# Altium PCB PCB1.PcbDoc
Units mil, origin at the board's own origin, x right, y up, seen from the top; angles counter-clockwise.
Board outline 1377.95 x 2381.89 mil, 2 copper layers (Top Layer, Bottom Layer), stack 65.792 mil thick; 17 components, 12 nets, 45 pads, 0 vias.
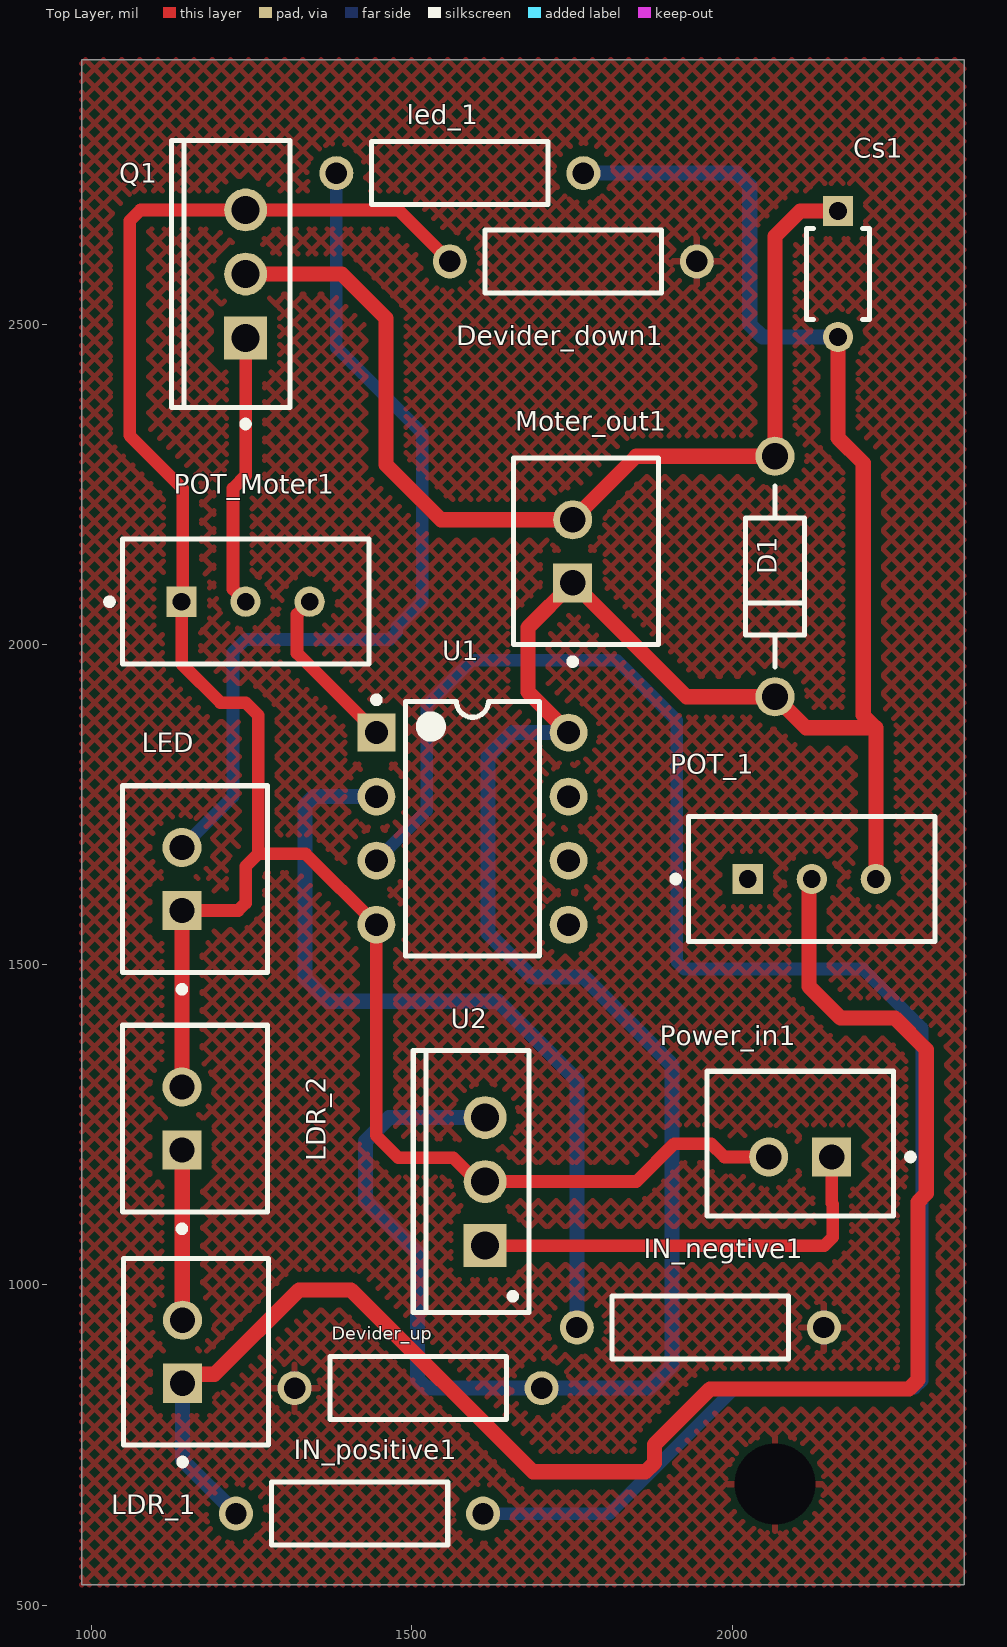
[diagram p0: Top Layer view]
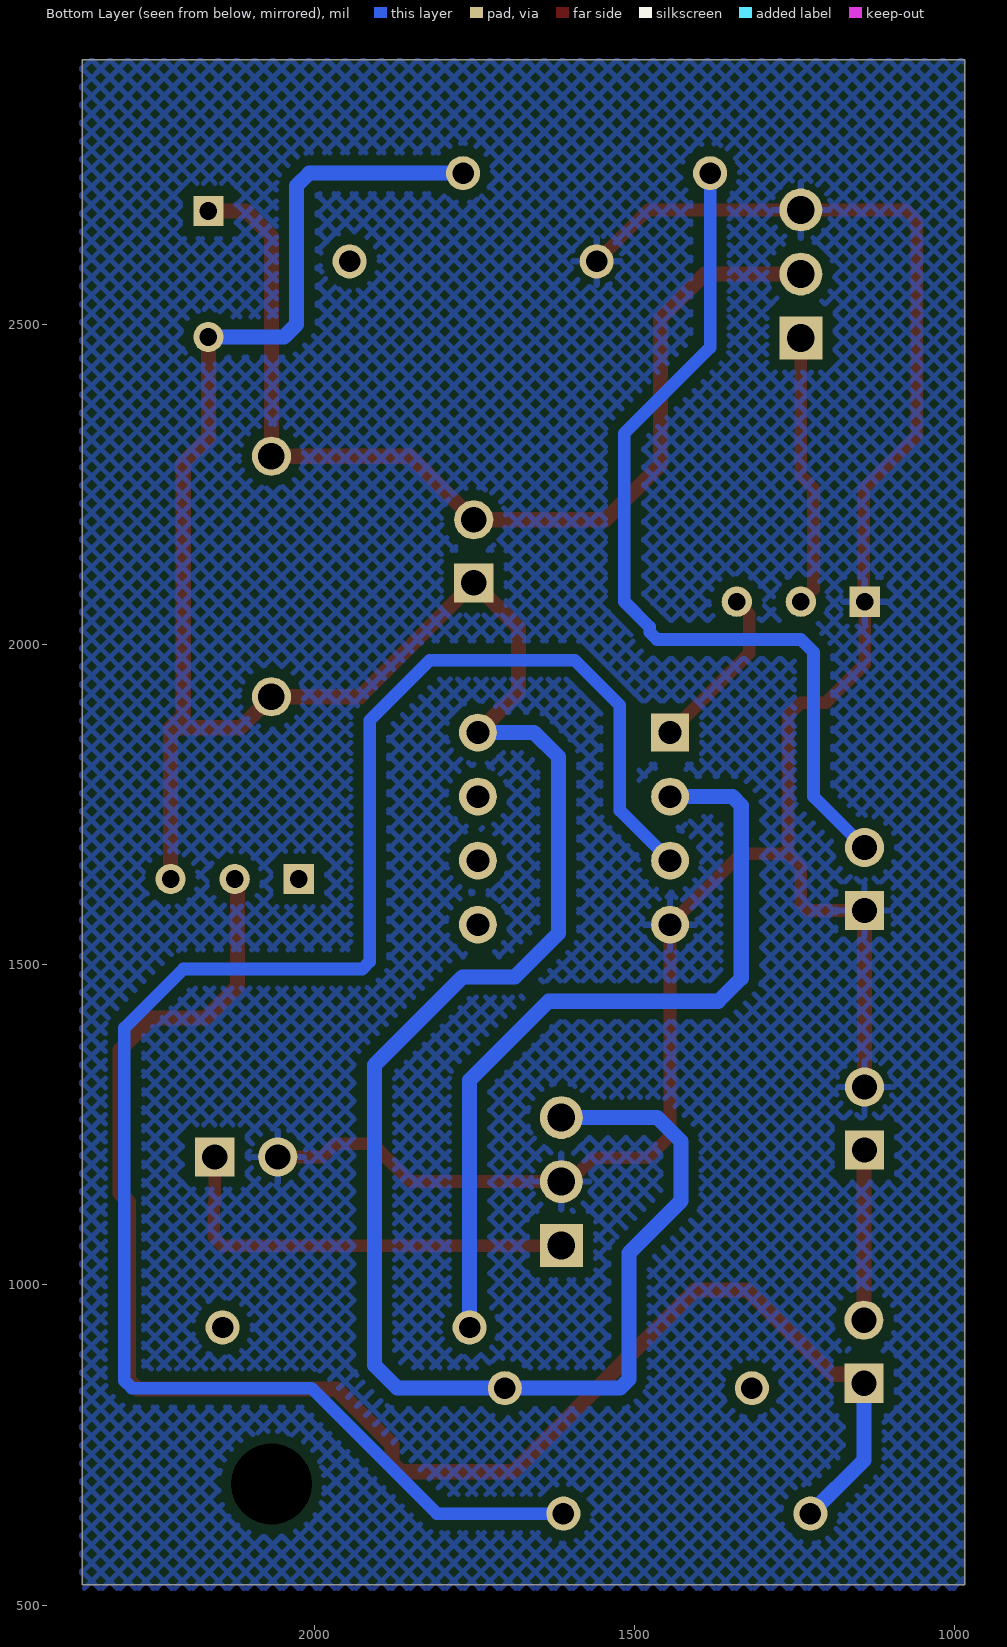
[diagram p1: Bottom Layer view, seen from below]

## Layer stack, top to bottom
Top Solder: solder mask 0.4, Solder Resist, Dk 3.5
Top Layer: signal copper 1.4
Dielectric 1: dielectric 62.9921, FR-4, Dk 4.8
Bottom Layer: signal copper 1.4
Bottom Solder: solder mask 0.4, Solder Resist, Dk 3.5

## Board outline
984.25,531.5 2362.2,531.5 2362.2,2913.39 984.25,2913.39

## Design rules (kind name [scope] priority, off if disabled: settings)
Clearance [All] p1: gap=15.75 ignorepadtopadclearanceinfootprint=FALSE
PolygonConnect [All] p1: connectstyle=Relief reliefconductorwidth=10 reliefentries=4 polygonreliefangle="90 Angle" airgapwidth=10
RoutingVias [All] p1: holewidth=27.56 width=39.37 viastyle="Through Hole" minholewidth=27.56 minwidth=39.37 maxholewidth=27.56 maxwidth=78.74
SilkToSolderMaskClearance [IsPad] p1: minsilkscreentomaskgap=7.87 clearancetoexposedcopper=TRUE
SolderMaskExpansion [All] p1: expansion=4 istentingtop=FALSE
Width [All] p1: maxlimit=78.74 minlimit=19.68 preferedwidth=39.37
29 further rules are at their usual default settings.

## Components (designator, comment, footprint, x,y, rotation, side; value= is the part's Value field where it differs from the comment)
Cs1 "27pF" FP-RCE0K1-MFG 2165.35,2578.74 r270 top
D1 "1N5819" ONSC-AXIAL_LEAD-2-59-10_P 2066.93,2106.3 r90 top
Devider_down1 "10K" OMTE-RES7X2.5-2 1751.97,2598.43 r0 top
Devider_up "10K" OMTE-RES7X2.5-2 1509.5,838.78 r0 top (schematic designator Devider_up1)
IN_negtive1 "10K" OMTE-RES7X2.5-2 1950.39,933.49 r180 top
IN_positive1 "10K" OMTE-RES7X2.5-2 1418.06,642.83 r0 top
LDR_1 "LDR_1" FP-B2B-XH-A_LF_SN-MFG 1162.4,895.67 r90 top
LDR_2 "Signal" FP-B2B-XH-A_LF_SN-MFG 1161.42,1259.84 r90 top
LED "LED" FP-B2B-XH-A_LF_SN-MFG 1161.42,1633.86 r90 top
led_1 "10K" OMTE-RES7X2.5-2 1574.8,2736.22 r0 top
Moter_out1 "moter" FP-B2B-XH-A_LF_SN-MFG 1771.65,2145.67 r90 top
POT_1 "10K" FP-3296W-MFG 2124.41,1634.06 r270 top
POT_Moter1 "10K" FP-3296W-MFG 1240.16,2067.13 r270 top
Power_in1 "Power" FP-B2B-XH-A_LF_SN-MFG 2106.3,1220.47 r180 top
Q1 "IRF840PBF" VISH-TO-220AB-3 1240.16,2578.74 r180 top
U1 "LM358N" ONSC-PDIP-8-626-05_M 1594.49,1712.6 r0 top
U2 "L7805CV" TO220 1614.17,1161.42 r90 top

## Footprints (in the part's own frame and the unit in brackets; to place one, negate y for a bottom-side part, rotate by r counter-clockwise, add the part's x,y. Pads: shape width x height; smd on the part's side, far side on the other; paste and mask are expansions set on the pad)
FP-3296W-MFG [mm]
  rect 1.2x1.2 hole 0.7 paste-1000 mask+0: 1(0.005,-2.54)
  round 1.2 hole 0.7 paste-1000 mask+0: 2(0.005,0) 3(0.005,2.54)
  silkscreen extent -2.48,-5.52 2.48,4.89, body extent -2.58,-4.99 2.58,4.99, height 0.25
FP-B2B-XH-A_LF_SN-MFG [mm]
  rect 1.55x1.55 hole 1 paste-1000 mask+0: 1(-1.25,0.525)
  round 1.55 hole 1 paste-1000 mask+0: 2(1.25,0.525)
  silkscreen extent -4.5,-2.88 3.7,2.88, body extent -3.8,-2.98 3.8,2.98, height 0.25
FP-RCE0K1-MFG [mm]
  rect 1.2x1.2 hole 0.7 paste-1000 mask+0: 1(-2.5,0)
  round 1.2 hole 0.7 paste-1000 mask+0: 2(2.5,0)
  silkscreen extent -1.8,-1.25 1.8,1.25, body extent -3.2,-1.35 3.2,1.35, height 0.25
OMTE-RES7X2.5-2 [mm] "Resistor, Axial; Body 7x2.5mm, Lead Dia. 0.6mm"
  round 1.35 hole 0.85: 1(-4.9,0) 2(4.9,0)
  silkscreen extent -3.5,-1.25 3.5,1.25, body extent -3.5,-1.25 3.5,1.25, height 2.5
ONSC-AXIAL_LEAD-2-59-10_P [mm] "AXIAL, 2-Leads, Diameter 2.35mm"
  round 1.55 hole 1.05: 1(-4.77,0) 2(4.77,0)
  silkscreen extent -3.59,-1.17 3.59,1.17
ONSC-PDIP-8-626-05_M [mm] "DIP, 8-Leads, Body 10x7.1mm, Pitch 2.54mm"
  rect 1.5x1.5 hole 0.9: 1(-3.81,3.81)
  round 1.5 hole 0.9: 2(-3.81,1.27) 3(-3.81,-1.27) 4(-3.81,-3.81) 5(3.81,-3.81) 6(3.81,-1.27) 7(3.81,1.27) 8(3.81,3.81)
  silkscreen extent -3.93,-5.05 2.65,5.23, body extent -3.95,-5 3.95,5, height 5.33
TO220 [mm] "TO, Thru-Hole, Vertical, Heatsink Mounted; 3 In-Line Leads; Pitch 2.54 mm"
  rect 1.7x1.7 hole 1.1: 1(-2.54,0)
  round 1.7 hole 1.1: 2(0,0) 3(2.54,0)
  silkscreen extent -5.2,-1.75 5.2,2.85, body extent -5.25,-1.8 5.25,2.9, height 19.7
VISH-TO-220AB-3 [mm] "FM, 3-Leads, Body 10.55x4.65mm, Pitch 2.54mm"
  rect 1.7x1.7 hole 1.1: 1(0,2.54)
  round 1.7 hole 1.1: 2(0,0) 3(0,-2.54)
  silkscreen extent -1.77,-5.3 2.94,6.07, body extent -1.74,-5.28 2.91,5.28, height 19.31

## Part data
Cs1: library part CMP-06035-026251-1, "Cap Ceramic 27pF 50V C0G ±5% Radial 5mm +125°C Automotive Bulk", Case/Package=Radial, Dielectric=C0G, Max Operating Temperature=125°C, Min Operating Temperature=-55°C, Package Quantity=1, Ratings=AEC-Q200, Resistor Type=Ceramic, Tolerance=5%, Voltage Rating=50V
D1: library part CMP-1055-00042-1, "Rectifier, 2-Pin Axial_Lead, Pb-Free, Bulk Bag", Manufacturer="On Semiconductor"
Devider_down1 Devider_up IN_negtive1 IN_positive1 led_1: library part CMP-2000-06865-1, "Little Demon(R) Carbon Composition Molded OD Series, 250 V, 10 KOhm, +/-5%, -70 to 130 degC, 2-Pin THD, RoHS, Bulk", Manufacturer=Ohmite, Operating Temperature=-, Package / Case=Axial, Package Description="2-Pin THD Resistor, Body 7 x 2.5 mm, Lead Dia. 0.6 mm", Package Reference=RES7X2.5, PartNumber=OD103JE, Power (Watts)=0.25W,1/4W, Power Rating=0.25W, Resistance (Ohms)=10k, Standard Package=100, Tolerance=±5%
LDR_1 LDR_2 LED Moter_out1 Power_in1: library part CMP-2000-05888-3, "CONN HEADER VERT 2POS 2.5MM", Color=Natural, Contact Resistance=20mR, Current Rating=3A, Housing Color=White, Insulation Resistance=1GR, Max Operating Temperature=85°C, Max Voltage Rating (AC)=250V, Min Operating Temperature=-25°C
POT_1 POT_Moter1: library part CMP-1747-00001-5, "TRIMMER 10K OHM 0.5W PC PIN TOP", Color=Blue, Insulation Resistance=1GR, Max Operating Temperature=125°C, Max Power Dissipation=500mW, Min Operating Temperature=-55°C, Package Quantity=50, Resistance=10kR, Resistance Tolerance=10%, Resistor Type=Cermet, Temperature Coefficient=100ppm/°C
Q1: library part CMP-2000-06467-1, "Power MOSFET, 500 V, -55 to 150 degC, 3-Pin FM, RoHS, Tape and Reel", Manufacturer=Vishay, Maximum Continuous Drain Current=8A, Maximum Drain Source Resistance=0.85Ω, Maximum Drain Source Voltage=500V, Maximum Gate Source Voltage=±20V, Maximum Operating Temperature=+150°C, Maximum Power Dissipation=125W, Minimum Gate Threshold Voltage=2V, Minimum Operating Temperature=-55°C, Package Description="3-Pin Flange Mount, Body 10.275 x 4.45 mm, Pitch 2.54 mm", Package Reference=TO-220AB-3, Package Type=TO-220AB, Typical Input Capacitance @ Vds=1300pF@25V
U1: library part CMP-1310-00098-1, "Single Supply Dual Operational Amplifier, 3 to 32 V, 0 to 70 degC, 8-Pin PDIP, Tube", Manufacturer="On Semiconductor"
U2: library part CMP-0244-00483-1, "Positive Voltage Regulator, 5V, 3-Pin TO-220"

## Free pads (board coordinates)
  round 60 hole 126 unplated: 1(2066.93,688.98)

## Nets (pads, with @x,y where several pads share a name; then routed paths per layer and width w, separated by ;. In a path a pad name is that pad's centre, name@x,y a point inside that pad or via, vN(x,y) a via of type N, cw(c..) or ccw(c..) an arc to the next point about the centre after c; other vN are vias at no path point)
Gnd: Devider_down1.1 LDR_2.2 LED.1 POT_Moter1.1 Power_in1.2 Q1.3 U1.4 U2.2 | length 3338.2
  Top Layer w19.68: LED.1 1228.63,1584.65 1240.16,1596.18 1240.16,1653.54 1259.84,1673.23 ; Devider_down1.1 1478.74,2678.74 1076.1,2678.74 1059.06,2661.7 1059.06,2326.77 1141.73,2244.09 1141.73,2068.5 POT_Moter1.1 1140.16,1970.08 1200.79,1909.45 1240.16,1909.45 1259.84,1889.76 1259.84,1673.23 ; Power_in1.2 1988.01,1199.8 1967.34,1220.47 1909.45,1220.47 1850.39,1161.42 U2.2 1601.39,1161.42 1564.51,1198.3 1478.87,1198.3 1444.49,1232.68 U1.4 1333.86,1673.23 1259.84,1673.23
  Top Layer w23.62: LED.1 LDR_2.2 LDR_2.2@1141.24,1309.55 ; LED.1@1141.24,1574.31 LED.1@1141.73,1574.8
NetCs1_1: Cs1.1 D1.2 Moter_out1.2 Q1.2 | length 1619.4
  Top Layer w23.62: Q1.2 1390.26,2578.74 1459.33,2509.67 1459.33,2280.83 1545.28,2194.88 Moter_out1.2 1850.2,2294.09 D1.2 2066.93,2637.8 2106.3,2677.17 Cs1.1
NetCs1_2: Cs1.2 D1.1 Devider_up.2 led_1.2 Moter_out1.1 POT_1.3 U1.8 U2.3 | length 4652.8
  Top Layer w23.62: U1.8 1681.1,1925.98 1681.1,2026.57 Moter_out1.1 1928.94,1918.5 D1.1 2115.35,1870.08 2224.41,1870.08 ; Cs1.2 2165.35,2322.83 2204.72,2283.46 2204.72,1889.76 2224.41,1870.08 ; POT_1.3@2224.41,1622.95 2224.41,1870.08
  Bottom Layer w23.62: U2.3 1464.4,1261.42 1427.29,1224.31 1427.29,1130.91 1508.38,1049.82 1508.38,852.62 1522.22,838.78 Devider_up.2 1870.42,838.78 1906.16,874.52 1906.16,1343.52 1768.66,1481.02 1686.97,1481.02 1618.87,1549.12 1618.87,1824.77 1656.7,1862.6 U1.8 ; led_1.2 2007.87,2736.22 2027.56,2716.54 2027.56,2500 2047.24,2480.32 Cs1.2
NetDevider_down1_2: Devider_down1.2 Devider_up.1 IN_negtive1.1 pad.1 | length 5.6
  Top Layer w19.68: Devider_down1.2 Devider_down1.2@1948.82,2602.36
NetIN_negtive1_2: IN_negtive1.2 U1.2 | length 1263.7
  Bottom Layer w23.62: U1.2 1444.29,1762.8 1346.99,1762.8 1333.15,1748.96 1333.15,1478.89 1369.07,1442.96 1634.22,1442.96 1757.48,1319.7 IN_negtive1.2
NetIN_positive1_1: IN_positive1.1 LDR_1.1 POT_1.2 | length 2555.8
  Top Layer w23.62: LDR_1.1 1155.78,860.5 1191.58,860.5 1323.35,992.28 1405,992.28 1689.13,708.15 1864.71,708.15 1878.55,721.99 1878.55,750.6 1965.56,837.62 2276.21,837.62 2290.04,851.45 2290.04,1129.44 2303.11,1142.51 2303.11,1367.85 2254.12,1416.84 2169.21,1416.84 2120.21,1465.84 2120.21,1629.66 POT_1.2
  Bottom Layer w23.62: LDR_1.1 1141.73,726.25 IN_positive1.1
NetIN_positive1_2: IN_positive1.2 U1.3 | length 2859.1
  Bottom Layer w19.68: U1.3 1522.8,1740.91 1522.8,1905 1593.57,1975.78 1819.42,1975.78 1913.52,1881.67 1913.52,1504.82 1925.06,1493.29 2204.49,1493.29 2296.57,1401.21 2296.57,850.32 2285.04,838.78 2004.55,838.78 1808.6,642.83 IN_positive1.2
NetLDR_1_2: LDR_1.2 LDR_2.1 | length 266.2
  Top Layer w23.62: LDR_2.1 1141.24,1210.14 1141.24,945.37 LDR_1.2
Netled_1_1: LED.2 led_1.1 | length 1395.5
  Bottom Layer w19.68: LED.2 1220.47,1762.8 1220.47,1988.19 1240.16,2007.87 1464.85,2007.87 1476.38,2019.41 1476.38,2027.56 1515.75,2066.93 1515.75,2330.12 1381.89,2463.98 led_1.1
NetPOT_Moter1_2: POT_Moter1.2 Q1.1 | length 428.1
  Top Layer w19.68: POT_Moter1.2 1220.47,2086.61 1220.47,2244.09 1240.16,2263.78 Q1.1
NetPOT_Moter1_3: POT_Moter1.3 U1.1 | length 263.9
  Top Layer w19.68: POT_Moter1.3 1320.47,2047.24 1320.47,1986.61 U1.1
NetPower_in1_1: Power_in1.1 U2.1 | length 674.4
  Top Layer w19.68: U2.1 2144.09,1061.42 2157.2,1074.52 2157.2,1125.98 2155.51,1127.67 Power_in1.1
pads on no net: POT_1.1 U1.5 U1.6 U1.7

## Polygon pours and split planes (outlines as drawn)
NetDevider_down1_2 on Top Layer "L01_NETDEVIDER_DOWN1_2_P000" (hatched 45Degree grid 20 track 8, pour order 0): 984.25,531.5 2362.2,531.5 2362.2,2913.39 984.25,2913.39
Gnd on Bottom Layer "L02_GND_P004" (hatched 45Degree grid 20 track 8, pour order 4): 984.96,532.17 990.9,526.23 2363.21,526.23 2363.21,2903.42 2354.54,2912.1 986.64,2912.1 986.64,532.01

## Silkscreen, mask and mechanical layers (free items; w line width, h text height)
Mechanical 1:
  lines w7.87: 4704.72,413.39 4724.41,433.07 ; 984.25,531.5 1948.82,531.5 2362.2,531.5 2362.2,2913.39 984.25,2913.39 984.25,531.5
